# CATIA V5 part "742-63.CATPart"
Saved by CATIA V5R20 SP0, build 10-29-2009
Part number: 742-63
Bounding box of the stored display mesh (mm): x -47.5 to 48, y -47.5 to 47.5, z -60 to 90
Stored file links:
  C:\Users\Utente\Desktop\IO LAVORO\3D X SITO CF\X SITO\742\742-63.CATPart
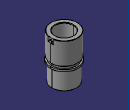
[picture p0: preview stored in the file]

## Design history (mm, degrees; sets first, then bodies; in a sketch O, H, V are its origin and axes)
Set1
  DatumSurface1 to DatumSurface38 "742-63"
Body1 (main body)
